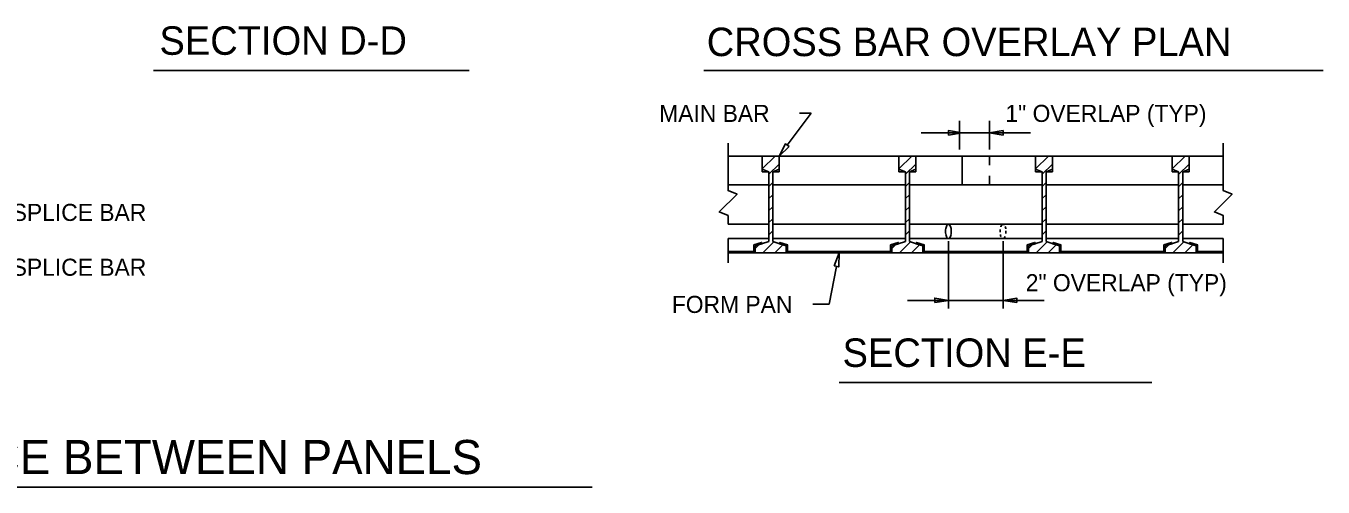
# Model space of a CAD drawing. Extents: x -24512 to -22484, y 4569 to 6351.
# Drawn here: x -24013.4 to -23785.7, y 5331 to 5412 of the extents above; entities that cross this region are included whole.
import ezdxf

# ---------------------------------------------------------------- set-up
doc = ezdxf.new("R2010")
doc.units = 0
for name, color, linetype in [('10', 7, 'Continuous'), ('3', 7, 'Continuous'), ('4', 7, 'Continuous'), ('6', 7, 'Continuous'), ('9', 7, 'Continuous')]:
    doc.layers.add(name, color=color, linetype=linetype)

# ---------------------------------------------------------------- blocks, each defined once
blk = doc.blocks.new('SYM029')
at = {"layer": '3'}
for p, q in [((45.29725, 11.51025), (45.748875, 11.96175)), ((45.29725, 11.937875), (45.32125, 11.96175)), ((45.52425, 11.3095), (45.8965, 11.68175)), ((45.52425, 10.881875), (45.6695, 11.027)), ((45.52425, 10.454125), (45.6695, 10.599375)), ((45.52425, 10.0265), (45.6695, 10.171625)), ((45.52425, 9.59875), (45.6695, 9.744)), ((45.52425, 9.171125), (45.6695, 9.31625)), ((45.04875, 8.6955), (45.18175, 8.8285)), ((45.31525, 8.534375), (45.7065, 8.925625)), ((45.743, 8.534375), (46.031, 8.8225))]:
    blk.add_line(p, q, dxfattribs=at)

msp = doc.modelspace()

# ---------------------------------------------------------------- linework, layer by layer
at = {"layer": '10'}
for p, q in [((-23991.07, 5404.17), (-23935.59, 5404.17)), ((-23894.39, 5404.16), (-23785.66, 5404.16)), ((-23870.61, 5349.35), (-23815.72, 5349.35)), ((-23914.02, 5331.01), (-24037.37, 5331.01))]:
    msp.add_line(p, q, dxfattribs=at)
at = {"layer": '4'}
for p, q in [((-23884.14, 5389.12), (-23890.13, 5389.12)), ((-23884.14, 5389.12), (-23881.17, 5389.12)), ((-23884.14, 5386.86), (-23884.14, 5389.12)), ((-23881.17, 5386.86), (-23881.17, 5389.12)), ((-23860.14, 5389.12), (-23881.17, 5389.12)), ((-23860.14, 5389.12), (-23857.17, 5389.12)), ((-23860.14, 5386.86), (-23860.14, 5389.12)), ((-23857.17, 5386.86), (-23857.17, 5389.12)), ((-23841.86, 5389.12), (-23857.17, 5389.12)), ((-23836.14, 5389.12), (-23851.45, 5389.12)), ((-23849.05, 5389.12), (-23849.05, 5384.12)), ((-23836.14, 5386.86), (-23836.14, 5389.12)), ((-23836.14, 5389.12), (-23833.17, 5389.12)), ((-23812.14, 5389.12), (-23833.17, 5389.12)), ((-23833.17, 5386.86), (-23833.17, 5389.12)), ((-23812.14, 5386.86), (-23812.14, 5389.12)), ((-23812.14, 5389.12), (-23809.17, 5389.12)), ((-23809.17, 5386.86), (-23809.17, 5389.12)), ((-23803.18, 5389.12), (-23809.17, 5389.12)), ((-23884.14, 5386.86), (-23883.01, 5386.36)), ((-23884.14, 5386.86), (-23884.14, 5386.36)), ((-23883.01, 5386.36), (-23884.14, 5386.36)), ((-23883.01, 5374.11), (-23883.01, 5386.36)), ((-23881.17, 5386.86), (-23882.29, 5386.36)), ((-23882.29, 5374.11), (-23882.29, 5386.36)), ((-23882.29, 5386.36), (-23881.17, 5386.36)), ((-23881.17, 5386.86), (-23881.17, 5386.36)), ((-23860.14, 5386.86), (-23859.01, 5386.36)), ((-23860.14, 5386.86), (-23860.14, 5386.36)), ((-23859.01, 5386.36), (-23860.14, 5386.36)), ((-23859.01, 5374.11), (-23859.01, 5386.36)), ((-23857.17, 5386.86), (-23858.29, 5386.36)), ((-23858.29, 5374.11), (-23858.29, 5386.36)), ((-23858.29, 5386.36), (-23857.17, 5386.36)), ((-23857.17, 5386.86), (-23857.17, 5386.36)), ((-23836.14, 5386.86), (-23835.01, 5386.36)), ((-23836.14, 5386.86), (-23836.14, 5386.36)), ((-23835.01, 5386.36), (-23836.14, 5386.36)), ((-23835.01, 5374.11), (-23835.01, 5386.36)), ((-23833.17, 5386.86), (-23834.29, 5386.36)), ((-23834.29, 5386.36), (-23833.17, 5386.36)), ((-23834.29, 5374.11), (-23834.29, 5386.36)), ((-23833.17, 5386.86), (-23833.17, 5386.36)), ((-23812.14, 5386.86), (-23812.14, 5386.36)), ((-23812.14, 5386.86), (-23811.02, 5386.36)), ((-23811.02, 5386.36), (-23812.14, 5386.36)), ((-23811.02, 5374.11), (-23811.02, 5386.36)), ((-23809.17, 5386.86), (-23810.3, 5386.36)), ((-23810.3, 5374.11), (-23810.3, 5386.36)), ((-23810.3, 5386.36), (-23809.17, 5386.36)), ((-23809.17, 5386.86), (-23809.17, 5386.36)), ((-23883.01, 5384.12), (-23890.13, 5384.12)), ((-23859.01, 5384.12), (-23882.29, 5384.12)), ((-23841.86, 5384.12), (-23858.29, 5384.12)), ((-23835.01, 5384.12), (-23851.45, 5384.12)), ((-23811.02, 5384.12), (-23834.29, 5384.12)), ((-23803.18, 5384.12), (-23810.3, 5384.12)), ((-23890.13, 5377.16), (-23883.01, 5377.16)), ((-23882.29, 5377.16), (-23859.01, 5377.16)), ((-23858.29, 5377.16), (-23835.01, 5377.16)), ((-23834.29, 5377.16), (-23811.02, 5377.16)), ((-23803.18, 5377.16), (-23810.3, 5377.16)), ((-23890.13, 5374.66), (-23883.01, 5374.66)), ((-23890.13, 5370.37), (-23890.13, 5374.66)), ((-23883.01, 5374.11), (-23885.37, 5373.37)), ((-23882.29, 5374.66), (-23859.01, 5374.66)), ((-23882.29, 5374.11), (-23879.93, 5373.37)), ((-23859.01, 5374.11), (-23861.37, 5373.37)), ((-23858.29, 5374.66), (-23835.01, 5374.66)), ((-23858.29, 5374.11), (-23855.94, 5373.37)), ((-23835.01, 5374.11), (-23837.37, 5373.37)), ((-23834.29, 5374.66), (-23811.02, 5374.66)), ((-23834.29, 5374.11), (-23831.94, 5373.37)), ((-23811.02, 5374.11), (-23813.37, 5373.37)), ((-23803.18, 5374.66), (-23810.3, 5374.66)), ((-23810.3, 5374.11), (-23807.94, 5373.37)), ((-23803.18, 5370.37), (-23803.18, 5374.66)), ((-23885.37, 5372.12), (-23885.37, 5373.37)), ((-23885.37, 5372.12), (-23879.93, 5372.12)), ((-23879.93, 5372.12), (-23879.93, 5373.37)), ((-23861.37, 5372.12), (-23861.37, 5373.37)), ((-23861.37, 5372.12), (-23855.94, 5372.12)), ((-23855.94, 5372.12), (-23855.94, 5373.37)), ((-23837.37, 5372.12), (-23837.37, 5373.37)), ((-23837.37, 5372.12), (-23831.94, 5372.12)), ((-23831.94, 5372.12), (-23831.94, 5373.37)), ((-23813.37, 5372.12), (-23813.37, 5373.37)), ((-23813.37, 5372.12), (-23807.94, 5372.12)), ((-23807.94, 5372.12), (-23807.94, 5373.37))]:
    msp.add_line(p, q, dxfattribs=at)
for points in [[(-23890.13, 5377.16), (-23890.13, 5378.69), (-23891.68, 5379.33), (-23888.57, 5382.43), (-23890.13, 5383.08), (-23890.13, 5391.39)], [(-23803.18, 5377.16), (-23803.18, 5378.69), (-23804.73, 5379.33), (-23801.63, 5382.43), (-23803.18, 5383.08), (-23803.18, 5391.39)], [(-23890.13, 5372.12), (-23885.37, 5372.12), (-23885.37, 5373.37), (-23884.19, 5373.74), (-23884.27, 5373.98), (-23885.62, 5373.55), (-23885.62, 5372.37), (-23890.13, 5372.37)], [(-23803.18, 5372.37), (-23807.69, 5372.37), (-23807.69, 5373.55), (-23809.04, 5373.98), (-23809.12, 5373.74)], [(-23809.12, 5373.74), (-23807.94, 5373.37), (-23807.94, 5372.12), (-23803.18, 5372.12)]]:
    msp.add_lwpolyline(points, dxfattribs=at)
for points in [[(-23881.11, 5373.74), (-23879.93, 5373.37), (-23879.93, 5372.12), (-23861.37, 5372.12), (-23861.37, 5373.37), (-23860.19, 5373.74), (-23860.27, 5373.98), (-23861.62, 5373.55), (-23861.62, 5372.37), (-23879.68, 5372.37), (-23879.68, 5373.55), (-23881.04, 5373.98)], [(-23857.11, 5373.74), (-23855.94, 5373.37), (-23855.94, 5372.12), (-23837.37, 5372.12), (-23837.37, 5373.37), (-23836.19, 5373.74), (-23836.27, 5373.98), (-23837.62, 5373.55), (-23837.62, 5372.37), (-23855.69, 5372.37), (-23855.69, 5373.55), (-23857.04, 5373.98)], [(-23833.12, 5373.74), (-23831.94, 5373.37), (-23831.94, 5372.12), (-23813.37, 5372.12), (-23813.37, 5373.37), (-23812.19, 5373.74), (-23812.27, 5373.98), (-23813.62, 5373.55), (-23813.62, 5372.37), (-23831.69, 5372.37), (-23831.69, 5373.55), (-23833.04, 5373.98)]]:
    msp.add_lwpolyline(points, close=True, dxfattribs=at)
for centre, radius, start, end in [((-23848.89, 5375.91), 3.07, 170.4548, 180), ((-23848.89, 5375.91), 3.07, 180, 189.5452), ((-23850.16, 5376.12), 1.78, 157.9048, 170.4548), ((-23850.96, 5376.45), 0.918, 135.5766, 157.9048), ((-23851.45, 5376.93), 0.229, 90, 135.5766), ((-23851.45, 5376.93), 0.229, 44.4234, 90), ((-23851.94, 5376.45), 0.918, 22.0952, 44.4234), ((-23852.74, 5376.12), 1.78, 9.5452, 22.0952), ((-23854.02, 5375.91), 3.07, 0, 9.5452), ((-23854.02, 5375.91), 3.07, 350.4548, 360), ((-23850.16, 5375.69), 1.78, 189.5452, 202.0952), ((-23850.96, 5375.37), 0.918, 202.0952, 224.4234), ((-23851.45, 5374.89), 0.229, 224.4234, 270), ((-23851.45, 5374.89), 0.229, 270, 315.5766), ((-23851.94, 5375.37), 0.918, 315.5766, 337.9048), ((-23852.74, 5375.69), 1.78, 337.9048, 350.4548)]:
    msp.add_arc(centre, radius, start, end, dxfattribs=at)
at = {"layer": '6'}
for p, q in [((-23844.26, 5389.12), (-23844.26, 5387.57)), ((-23844.26, 5385.7), (-23844.26, 5384.12))]:
    msp.add_line(p, q, dxfattribs=at)
for centre, radius, start, end in [((-23839.29, 5375.91), 3.07, 174.1368, 180), ((-23839.29, 5375.91), 3.07, 180, 182.3513), ((-23840.57, 5376.12), 1.78, 157.9048, 160.4267), ((-23841.37, 5376.45), 0.918, 135.5766, 157.9048), ((-23841.86, 5376.93), 0.229, 90, 135.5766), ((-23841.86, 5376.93), 0.229, 44.4234, 90), ((-23842.35, 5376.45), 0.918, 42.9698, 44.4234), ((-23843.15, 5376.12), 1.78, 9.5452, 21.0022), ((-23844.42, 5375.91), 3.07, 9.0274, 9.5452), ((-23844.42, 5375.91), 3.07, 353.061, 0), ((-23844.42, 5375.91), 3.07, 0, 1.3763), ((-23840.57, 5375.69), 1.78, 190.2263, 202.0952), ((-23841.37, 5375.37), 0.918, 202.0952, 202.8435), ((-23841.86, 5374.89), 0.229, 230.2328, 270), ((-23841.86, 5374.89), 0.229, 270, 315.5766), ((-23842.35, 5375.37), 0.918, 315.5766, 337.9048), ((-23843.15, 5375.69), 1.78, 337.9048, 338.022)]:
    msp.add_arc(centre, radius, start, end, dxfattribs=at)
at = {"layer": '9'}
for p, q in [((-23879.74, 5391.04), (-23875.54, 5396.69)), ((-23875.54, 5396.69), (-23877.61, 5396.69)), ((-23849.53, 5390.31), (-23849.53, 5395.34)), ((-23844.26, 5390.31), (-23844.26, 5395.34)), ((-23856.25, 5393.21), (-23849.05, 5393.21)), ((-23849.05, 5393.21), (-23844.26, 5393.21)), ((-23837.06, 5393.21), (-23844.26, 5393.21)), ((-23851.45, 5374.21), (-23851.45, 5362.38)), ((-23841.86, 5374.21), (-23841.86, 5362.38)), ((-23871.11, 5369.76), (-23872.41, 5363.14)), ((-23872.41, 5363.14), (-23875.25, 5363.14)), ((-23858.64, 5363.8), (-23851.45, 5363.8)), ((-23856.25, 5363.8), (-23841.86, 5363.8)), ((-23851.45, 5363.8), (-23841.86, 5363.8)), ((-23834.66, 5363.8), (-23841.86, 5363.8))]:
    msp.add_line(p, q, dxfattribs=at)
for points in [[(-23851.45, 5392.81), (-23851.45, 5393.61), (-23849.05, 5393.21)], [(-23841.86, 5392.81), (-23841.86, 5393.61), (-23844.26, 5393.21)], [(-23879.42, 5390.8), (-23880.06, 5391.28), (-23881.17, 5389.12)], [(-23871.51, 5369.84), (-23870.72, 5369.68), (-23870.65, 5372.12)], [(-23853.85, 5363.4), (-23853.85, 5364.2), (-23851.45, 5363.8)], [(-23839.46, 5363.4), (-23839.46, 5364.2), (-23841.86, 5363.8)]]:
    msp.add_lwpolyline(points, close=True, dxfattribs=at)

# ---------------------------------------------------------------- block references
at = {"layer": '3', "xscale": 4.959842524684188, "yscale": 4.959842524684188}
for p in [(-24108.81, 5329.79), (-24084.81, 5329.79), (-24060.81, 5329.79), (-24036.81, 5329.79)]:
    msp.add_blockref('SYM029', p, dxfattribs=at)

# ---------------------------------------------------------------- texts
at = {"layer": '10'}
msp.add_text('SPLICE BETWEEN PANELS', height=6.0008, dxfattribs=at).set_placement((-24037.71, 5333.28))
at = {"layer": '9'}
for s, height, p in [('SECTION D-D', 5, (-23990, 5406.93)), ('CROSS BAR OVERLAY PLAN', 5, (-23893.89, 5406.7)), ('MAIN BAR', 3, (-23902.24, 5395.14)), ('1" OVERLAP (TYP)', 2.9999, (-23841.44, 5395.14)), ('#4 SPLICE BAR', 2.9999, (-24021.52, 5377.75)), ('#4 SPLICE BAR', 2.9999, (-24021.52, 5368.12)), ('2" OVERLAP (TYP)', 2.9999, (-23837.87, 5365.4)), ('FORM PAN', 3, (-23900.02, 5361.59)), ('SECTION E-E', 5, (-23870.04, 5352.11))]:
    msp.add_text(s, height=height, dxfattribs=at).set_placement(p)

doc.saveas('drawing.dxf')
